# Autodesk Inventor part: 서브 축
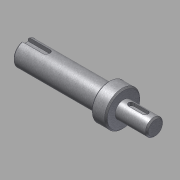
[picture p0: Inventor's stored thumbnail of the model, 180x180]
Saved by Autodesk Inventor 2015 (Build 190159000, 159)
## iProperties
Created: 2014-10
Part Number: 서브 축
Document SubType Name: Modeling
Designer: KYOUNG IL JANG
Density: 1 g/cm^3
Mass: 19.9624 g
Surface Area: 57.7178 cm^2
Volume: 19.9624 cm^3
Material: 강철, 연강
Appearance: 금속-강(스테인리스, 브러시됨)
Author: SeoGD™ [www.esajin.kr]
Revision Number: 1
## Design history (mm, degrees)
sketch "스케치1"
  geometry: L1 (-16.331, 0)-(-108.831, 0); L2 (-16.331, 0)-(-16.331, -6); L3 (-16.331, -6)-(-38.831, -6); L4 (-38.831, -12.5)-(-46.5, -12.5); L5 (-46.5, -8.5)-(-108.831, -8.5); L6 (-108.831, -8.5)-(-108.831, 0); L7 (-46.5, -8.5)-(-46.5, -12.5); L8 (-38.831, -6)-(-38.831, -12.5); L9 (-46.5, 12.249)-(-46.5, -12.249) reference; L10 (-38.831, -17)-(-38.831, 17) reference; 2 further points
  constraints: 17 end point, 4 perpendicular, 2 collinear, 2 parallel, 1 horizontal, 1 midpoint, 1 point on line
  dimensions: "d1" = 12 diameter of L3 L1; "d2" = 25 diameter of L4 L1; "d3" = 17 diameter of L5 L1; "d18" = 22.5 distance of L2.end L3.end; "d20" = 70 distance between parallel lines of L6 L8; "d21" = 7.66872 distance of L4.start L4.end (derived)
revolve "회전1" sketch "스케치1" stored, may be unused: angle "d5" = 90 deg
chamfer "모따기1" distance "d6" = 1; stored, may be unused: second distance "d7" = 2, angle "d8" = 45 deg
node "작업 평면1"
sketch "스케치2"
  geometry: L1 (11.25, 5)-(11.25, -5) reference; L2 (-5.75, -2)-(4.25, -2); L3 (4.25, 2)-(-5.75, 2); A1 r 2 centre (4.25, 0) between (4.25, -2) and (4.25, 2); A2 r 2 centre (-5.75, 0) between (-5.75, 2) and (-5.75, -2); 2 further points
  constraints: 4 end point, 4 point on circle, 4 tangent, 2 centre point, 1 horizontal alignment, 1 midpoint, 1 parallel, 1 perpendicular
  dimensions: "d9" = 4 distance between parallel lines of L2 L3; "d10" = 14 dimension on A1 A2; "d11" = 5 distance edge to line of A1 L1
extrude "돌출1" cut sketch "스케치2" distance "d12" = 2.5; taper "d13" = 0 deg
node "작업 평면2"
sketch "스케치3"
  geometry: L1 (-31.166, -7.5)-(-31.166, 7.5) reference; L2 (-31.166, 2.5)-(-15.666, 2.5); L3 (-15.666, -2.5)-(-31.166, -2.5); A1 r 2.5 centre (-15.666, 0) between (-15.666, -2.5) and (-15.666, 2.5); 2 further points
  constraints: 4 end point, 2 perpendicular, 2 point on circle, 2 point on line, 2 tangent, 1 centre point, 1 horizontal alignment, 1 midpoint
  dimensions: "d14" = 5 distance between parallel lines of L3 L2; "d15" = 18 dimension on A1 L1
extrude "돌출2" cut sketch "스케치3" distance "d16" = 3; taper "d17" = 0 deg
sketch "스케치4"
  geometry: C1 r 12.5 at (0, 0) reference; 1 further point
extrude "돌출3" join sketch "스케치4" distance "d22" = 3; taper "d23" = 0 deg
chamfer "모따기2" distance "d24" = 1; stored, may be unused: second distance "d25" = 2, angle "d26" = 45 deg
node "솔리드1"
node "참조4"
node "참조5"
